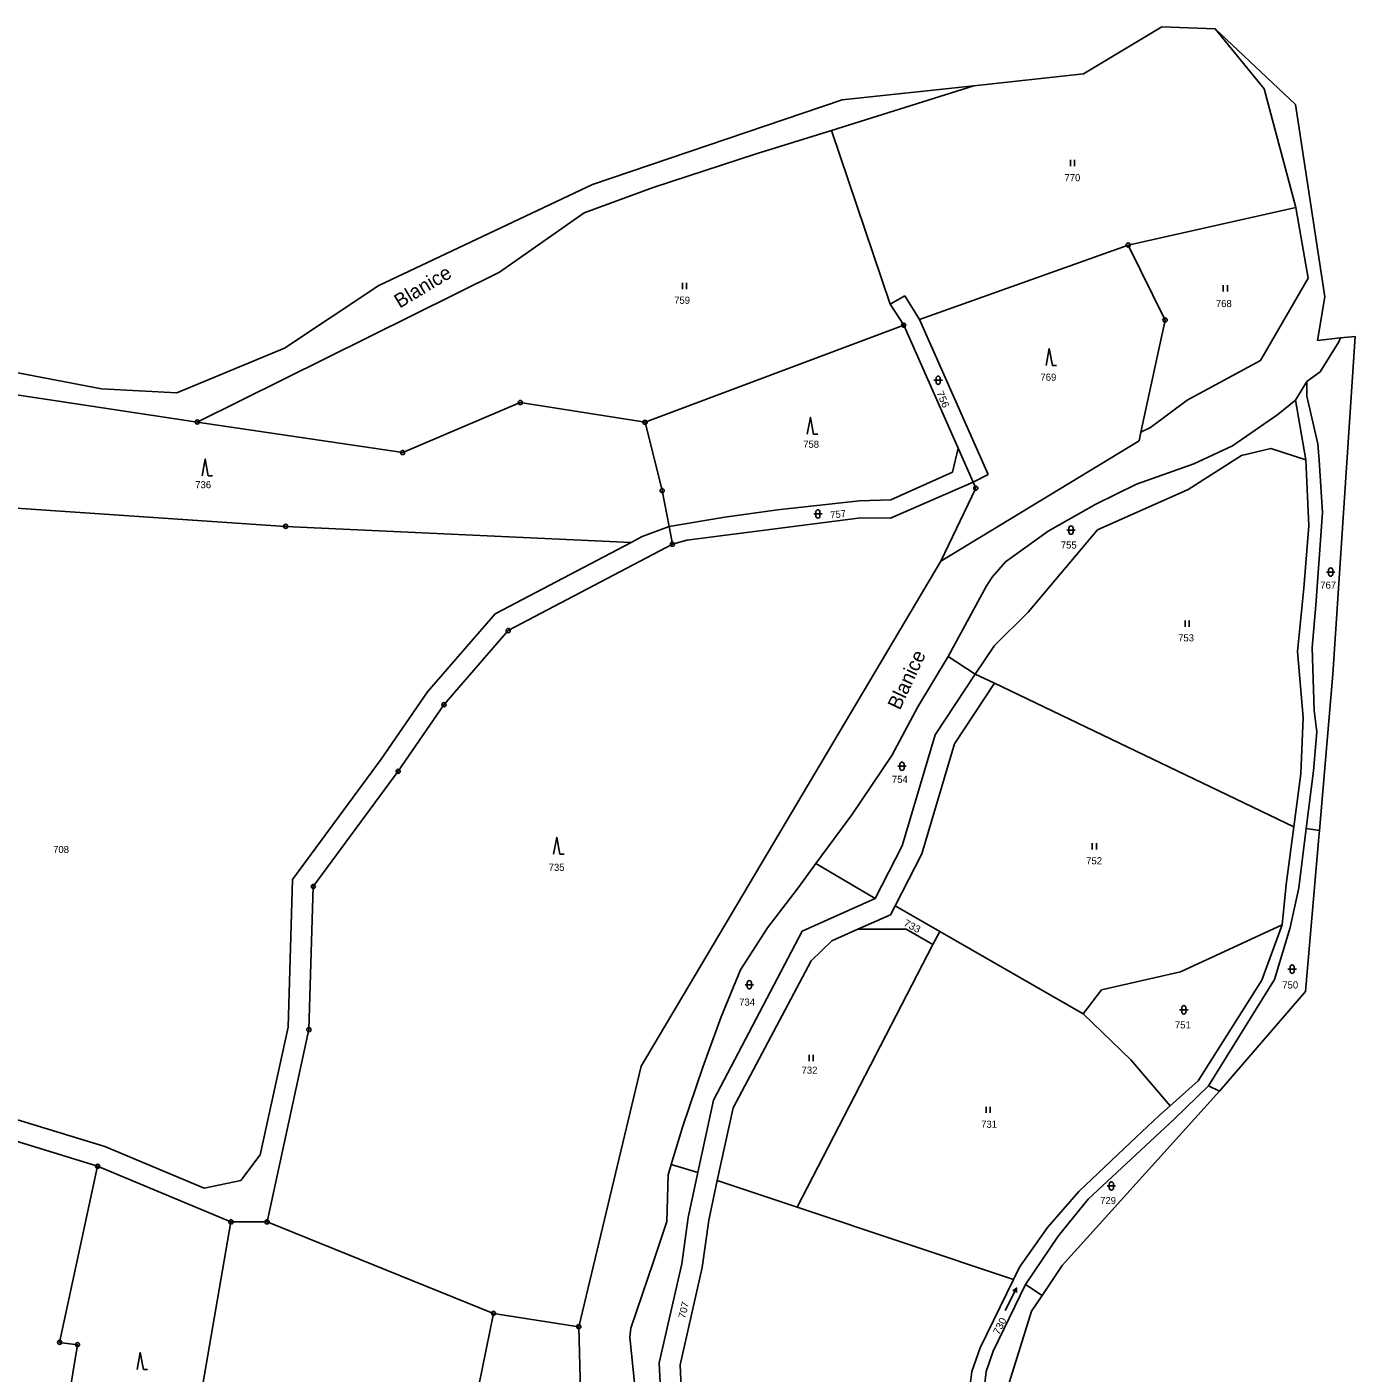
# Model space of a CAD drawing. Extents: x -719614 to -717765, y -1095834 to -1093862.
# Drawn here: x -718435.2 to -718117.4, y -1094701.4 to -1094379.3 of the extents above; entities that cross this region are included whole.
import ezdxf
from ezdxf.enums import TextEntityAlignment as Align

# ---------------------------------------------------------------- set-up
doc = ezdxf.new("R2010")
doc.units = 0
doc.header["$LTSCALE"] = 0.68
for name, color, linetype, lineweight in [('1', 7, 'Continuous', 25), ('3', 7, 'Continuous', 25), ('8', 7, 'Continuous', 25)]:
    doc.layers.add(name, color=color, linetype=linetype, lineweight=lineweight)
doc.layers.add('2', color=7, linetype='Continuous')
doc.layers.add('7', color=7, linetype='Continuous')

msp = doc.modelspace()

# ---------------------------------------------------------------- linework, layer by layer
at = {"layer": '1'}
for p, q in [((-718163.64, -1094379.29), (-718182.36, -1094390.55)), ((-718150.87, -1094379.77), (-718163.64, -1094379.29)), ((-718150.87, -1094379.77), (-718139.16, -1094394.12)), ((-718131.66, -1094397.89), (-718150.87, -1094379.77)), ((-718182.36, -1094390.55), (-718208.63, -1094393.36)), ((-718242.73, -1094404.04), (-718208.63, -1094393.36)), ((-718208.63, -1094393.36), (-718240.17, -1094396.73)), ((-718139.16, -1094394.12), (-718131.54, -1094422.53)), ((-718240.17, -1094396.73), (-718299.9, -1094416.98)), ((-718242.73, -1094404.04), (-718260.73, -1094409.67)), ((-718228.65, -1094445.61), (-718242.73, -1094404.04)), ((-718260.73, -1094409.67), (-718285.38, -1094417.73)), ((-718299.9, -1094416.98), (-718351.01, -1094441.13)), ((-718285.38, -1094417.73), (-718301.9, -1094423.77)), ((-718301.9, -1094423.77), (-718322.17, -1094438)), ((-718171.69, -1094431.47), (-718131.54, -1094422.53)), ((-718131.54, -1094422.53), (-718128.62, -1094439.38)), ((-718171.69, -1094431.47), (-718221.64, -1094449.3)), ((-718162.87, -1094449.43), (-718171.69, -1094431.47)), ((-718322.17, -1094438), (-718394.47, -1094473.83)), ((-718351.01, -1094441.13), (-718373.64, -1094456.15)), ((-718128.62, -1094439.38), (-718140.01, -1094459.1)), ((-718225.17, -1094443.64), (-718228.65, -1094445.61)), ((-718221.64, -1094449.3), (-718225.17, -1094443.64)), ((-718225.42, -1094450.65), (-718228.65, -1094445.61)), ((-718225.42, -1094450.65), (-718287.31, -1094473.89)), ((-718212.4, -1094480.08), (-718225.42, -1094450.65)), ((-718205.24, -1094486.39), (-718221.64, -1094449.3)), ((-718168.66, -1094476.22), (-718162.87, -1094449.43)), ((-718120.91, -1094453.71), (-718126.38, -1094454.33)), ((-718117.4, -1094453.32), (-718122.7, -1094534.11)), ((-718120.91, -1094453.71), (-718121.29, -1094454.67)), ((-718117.4, -1094453.32), (-718120.91, -1094453.71)), ((-718373.64, -1094456.15), (-718399.35, -1094466.81)), ((-718121.29, -1094454.67), (-718125.75, -1094461.81)), ((-718417.41, -1094465.85), (-718450.5, -1094459.53)), ((-718140.01, -1094459.1), (-718157.58, -1094468.63)), ((-718125.75, -1094461.81), (-718128.93, -1094464.13)), ((-718394.47, -1094473.83), (-718457.79, -1094464.33)), ((-718399.35, -1094466.81), (-718417.41, -1094465.85)), ((-718128.93, -1094464.13), (-718131.66, -1094468.58)), ((-718128.93, -1094464.13), (-718128.94, -1094467.67)), ((-718345.31, -1094481.13), (-718317.19, -1094469.16)), ((-718317.19, -1094469.16), (-718287.31, -1094473.89)), ((-718157.58, -1094468.63), (-718166.37, -1094475.12)), ((-718131.66, -1094468.58), (-718135.91, -1094472)), ((-718129.19, -1094482.89), (-718131.66, -1094468.58)), ((-718128.94, -1094467.67), (-718126.35, -1094479.01)), ((-718135.91, -1094472), (-718146.76, -1094479.49)), ((-718394.47, -1094473.83), (-718345.31, -1094481.13)), ((-718287.31, -1094473.89), (-718283.22, -1094490.22)), ((-718169.11, -1094478.3), (-718168.66, -1094476.22)), ((-718166.37, -1094475.12), (-718168.66, -1094476.22)), ((-718216.51, -1094507.09), (-718169.11, -1094478.3)), ((-718212.4, -1094480.08), (-718213.71, -1094485.83)), ((-718208.81, -1094488.2), (-718212.4, -1094480.08)), ((-718146.76, -1094479.49), (-718155.99, -1094483.8)), ((-718126.35, -1094479.01), (-718125.99, -1094482.97)), ((-718144.58, -1094481.83), (-718157.37, -1094489.97)), ((-718137.58, -1094480.17), (-718144.58, -1094481.83)), ((-718129.19, -1094482.89), (-718137.58, -1094480.17)), ((-718128.43, -1094498.63), (-718129.19, -1094482.89)), ((-718125.99, -1094482.97), (-718125.23, -1094495.48)), ((-718213.71, -1094485.83), (-718228.5, -1094492.45)), ((-718208.81, -1094488.2), (-718205.24, -1094486.39)), ((-718155.99, -1094483.8), (-718169.72, -1094488.68)), ((-718208.81, -1094488.2), (-718228.59, -1094496.86)), ((-718216.51, -1094507.09), (-718208.17, -1094489.65)), ((-718208.17, -1094489.65), (-718208.81, -1094488.2)), ((-718169.72, -1094488.68), (-718179.44, -1094493.45)), ((-718478.47, -1094491.73), (-718373.34, -1094498.79)), ((-718283.22, -1094490.22), (-718281.57, -1094498.84)), ((-718235.99, -1094492.7), (-718255.63, -1094494.87)), ((-718228.5, -1094492.45), (-718235.99, -1094492.7)), ((-718157.37, -1094489.97), (-718179.03, -1094499.58)), ((-718255.63, -1094494.87), (-718268.25, -1094496.56)), ((-718179.44, -1094493.45), (-718190.87, -1094499.93)), ((-718125.23, -1094495.48), (-718126.77, -1094517.65)), ((-718373.34, -1094498.79), (-718290.64, -1094502.61)), ((-718288.02, -1094501.23), (-718281.57, -1094498.84)), ((-718268.25, -1094496.56), (-718281.57, -1094498.84)), ((-718281.57, -1094498.84), (-718280.76, -1094503.06)), ((-718235.67, -1094496.71), (-718277.29, -1094502.12)), ((-718228.59, -1094496.86), (-718235.67, -1094496.71)), ((-718129.63, -1094513.59), (-718128.43, -1094498.63)), ((-718323.22, -1094519.73), (-718290.64, -1094502.61)), ((-718290.64, -1094502.61), (-718288.02, -1094501.23)), ((-718277.29, -1094502.12), (-718280.76, -1094503.06)), ((-718190.87, -1094499.93), (-718201.03, -1094507.28)), ((-718179.03, -1094499.58), (-718195.62, -1094519.29)), ((-718280.76, -1094503.06), (-718320.06, -1094523.72)), ((-718288.21, -1094627.97), (-718216.51, -1094507.09)), ((-718201.03, -1094507.28), (-718204.27, -1094510.96)), ((-718204.27, -1094510.96), (-718205.71, -1094513.17)), ((-718205.71, -1094513.17), (-718214.8, -1094529.89)), ((-718131.2, -1094528.71), (-718129.63, -1094513.59)), ((-718126.77, -1094517.65), (-718127.7, -1094527.79)), ((-718339.4, -1094538.4), (-718323.22, -1094519.73)), ((-718195.62, -1094519.29), (-718203.69, -1094527.32)), ((-718320.06, -1094523.72), (-718335.44, -1094541.46)), ((-718203.69, -1094527.32), (-718208.32, -1094534.13)), ((-718127.7, -1094527.79), (-718127.17, -1094542.81)), ((-718214.8, -1094529.89), (-718222.01, -1094541.95)), ((-718214.8, -1094529.89), (-718208.32, -1094534.13)), ((-718129.83, -1094544.55), (-718131.2, -1094528.71)), ((-718217.88, -1094548.64), (-718208.32, -1094534.13)), ((-718208.32, -1094534.13), (-718203.67, -1094536.34)), ((-718125.92, -1094571.53), (-718122.7, -1094534.11)), ((-718203.67, -1094536.34), (-718213.3, -1094550.78)), ((-718203.67, -1094536.34), (-718132.06, -1094570.7)), ((-718350.47, -1094554.49), (-718339.4, -1094538.4)), ((-718335.44, -1094541.46), (-718346.4, -1094557.39)), ((-718222.01, -1094541.95), (-718228.22, -1094553.62)), ((-718130.38, -1094557.97), (-718129.83, -1094544.55)), ((-718127.17, -1094542.81), (-718126.55, -1094547.95)), ((-718225.78, -1094575.26), (-718217.88, -1094548.64)), ((-718213.3, -1094550.78), (-718221.12, -1094577.12)), ((-718126.55, -1094547.95), (-718127.39, -1094557.29)), ((-718228.22, -1094553.62), (-718237.86, -1094567.83)), ((-718371.66, -1094583.24), (-718350.47, -1094554.49)), ((-718346.4, -1094557.39), (-718366.71, -1094584.95)), ((-718127.39, -1094557.29), (-718129.13, -1094571.11)), ((-718132.06, -1094570.7), (-718130.38, -1094557.97)), ((-718133.87, -1094584.48), (-718132.06, -1094570.7)), ((-718129.13, -1094571.11), (-718130.9, -1094585.23)), ((-718126.06, -1094573.17), (-718129.29, -1094610.09)), ((-718129.13, -1094571.11), (-718125.92, -1094571.53)), ((-718126.06, -1094573.17), (-718125.92, -1094571.53)), ((-718232.21, -1094587.86), (-718225.78, -1094575.26)), ((-718246.42, -1094579.44), (-718250.7, -1094585.24)), ((-718221.12, -1094577.12), (-718227.48, -1094589.61)), ((-718372.74, -1094618.58), (-718371.66, -1094583.24)), ((-718366.71, -1094584.95), (-718367.76, -1094619.19)), ((-718250.7, -1094585.24), (-718257.98, -1094594.88)), ((-718134.87, -1094594.13), (-718133.87, -1094584.48)), ((-718130.9, -1094585.23), (-718132.97, -1094594.74)), ((-718249.72, -1094595.65), (-718232.21, -1094587.86)), ((-718227.48, -1094589.61), (-718228.56, -1094591.71)), ((-718216.8, -1094595.73), (-718227.48, -1094589.61)), ((-718228.56, -1094591.71), (-718236.37, -1094595.18)), ((-718270.97, -1094636.07), (-718249.72, -1094595.65)), ((-718257.98, -1094594.88), (-718264.47, -1094604.85)), ((-718236.37, -1094595.18), (-718242.62, -1094597.96)), ((-718236.37, -1094595.18), (-718224.8, -1094595.18)), ((-718224.8, -1094595.18), (-718218.41, -1094598.84)), ((-718218.41, -1094598.84), (-718216.8, -1094595.73)), ((-718216.8, -1094595.73), (-718182.49, -1094615.4)), ((-718134.87, -1094594.13), (-718159.16, -1094605.4)), ((-718139.71, -1094607.37), (-718134.87, -1094594.13)), ((-718132.97, -1094594.74), (-718136.69, -1094607.24)), ((-718218.41, -1094598.84), (-718250.93, -1094661.69)), ((-718242.62, -1094597.96), (-718247.55, -1094602.75)), ((-718264.47, -1094604.85), (-718269.11, -1094616.13)), ((-718247.55, -1094602.75), (-718266.25, -1094637.88)), ((-718159.16, -1094605.4), (-718178.1, -1094609.66)), ((-718154.99, -1094631.44), (-718139.71, -1094607.37)), ((-718136.69, -1094607.24), (-718152.49, -1094632.62)), ((-718178.1, -1094609.66), (-718182.49, -1094615.4)), ((-718129.29, -1094610.09), (-718149.87, -1094633.94)), ((-718182.49, -1094615.4), (-718171.06, -1094626.42)), ((-718379.39, -1094649.16), (-718372.74, -1094618.58)), ((-718269.11, -1094616.13), (-718273.48, -1094628.14)), ((-718367.76, -1094619.19), (-718377.76, -1094665.2)), ((-718303.17, -1094690.28), (-718288.21, -1094627.97)), ((-718273.48, -1094628.14), (-718278.27, -1094642.28)), ((-718171.06, -1094626.42), (-718161.67, -1094637.39)), ((-718161.67, -1094637.39), (-718154.99, -1094631.44)), ((-718149.87, -1094633.94), (-718187.47, -1094675.62)), ((-718152.49, -1094632.62), (-718160.65, -1094640.54)), ((-718152.49, -1094632.62), (-718149.87, -1094633.94)), ((-718450.16, -1094636.86), (-718416.62, -1094647.19)), ((-718274.7, -1094653.36), (-718270.97, -1094636.07)), ((-718266.25, -1094637.88), (-718270.02, -1094655.33)), ((-718164.37, -1094639.8), (-718161.67, -1094637.39)), ((-718160.65, -1094640.54), (-718181.3, -1094659.75)), ((-718171.16, -1094646.21), (-718164.37, -1094639.8)), ((-718418.32, -1094651.9), (-718451.67, -1094641.63)), ((-718278.27, -1094642.28), (-718281.04, -1094651.48)), ((-718416.62, -1094647.19), (-718392.85, -1094657.1)), ((-718183.53, -1094657.89), (-718171.16, -1094646.21)), ((-718384.07, -1094655.33), (-718379.39, -1094649.16)), ((-718427.41, -1094694.02), (-718418.32, -1094651.9)), ((-718386.43, -1094665.2), (-718418.32, -1094651.9)), ((-718281.78, -1094653.94), (-718282.1, -1094665.12)), ((-718281.04, -1094651.48), (-718281.78, -1094653.94)), ((-718274.7, -1094653.36), (-718281.04, -1094651.48)), ((-718277.02, -1094664.11), (-718274.7, -1094653.36)), ((-718392.85, -1094657.1), (-718384.07, -1094655.33)), ((-718270.02, -1094655.33), (-718272.07, -1094664.79)), ((-718250.93, -1094661.69), (-718270.02, -1094655.33)), ((-718191, -1094666.56), (-718183.53, -1094657.89)), ((-718181.3, -1094659.75), (-718188.47, -1094668.63)), ((-718250.93, -1094661.69), (-718199.15, -1094678.94)), ((-718401.57, -1094752.45), (-718386.43, -1094665.2)), ((-718377.76, -1094665.2), (-718386.43, -1094665.2)), ((-718377.76, -1094665.2), (-718323.58, -1094687.09)), ((-718282.1, -1094665.12), (-718285.3, -1094674.7)), ((-718278.55, -1094675.24), (-718277.02, -1094664.11)), ((-718272.07, -1094664.79), (-718273.63, -1094676.13)), ((-718197.73, -1094676.03), (-718191, -1094666.56)), ((-718188.47, -1094668.63), (-718196.25, -1094680.16)), ((-718285.3, -1094674.7), (-718290.71, -1094690.65)), ((-718283.9, -1094698.94), (-718278.55, -1094675.24)), ((-718273.63, -1094676.13), (-718278.88, -1094699.39)), ((-718199.15, -1094678.94), (-718197.73, -1094676.03)), ((-718192.32, -1094682.83), (-718187.47, -1094675.62)), ((-718207.16, -1094695.34), (-718199.15, -1094678.94)), ((-718204, -1094696.13), (-718196.25, -1094680.16)), ((-718196.25, -1094680.16), (-718192.32, -1094682.83)), ((-718194.83, -1094686.56), (-718192.32, -1094682.83)), ((-718323.58, -1094687.09), (-718338.19, -1094759.09)), ((-718303.17, -1094690.28), (-718323.58, -1094687.09)), ((-718194.83, -1094686.56), (-718201.68, -1094708.56)), ((-718302.75, -1094705.74), (-718303.17, -1094690.28)), ((-718290.71, -1094690.65), (-718290.93, -1094692.81)), ((-718431.06, -1094742.32), (-718423.14, -1094694.58)), ((-718423.14, -1094694.58), (-718427.41, -1094694.02)), ((-718290.93, -1094692.81), (-718289.77, -1094704.51)), ((-718209.14, -1094700.98), (-718207.16, -1094695.34)), ((-718283.36, -1094711.58), (-718283.9, -1094698.94)), ((-718205.66, -1094701), (-718204, -1094696.13)), ((-718278.88, -1094699.39), (-718278.37, -1094711.2)), ((-718211.58, -1094721.22), (-718209.14, -1094700.98)), ((-718208.16, -1094722.43), (-718205.66, -1094701))]:
    msp.add_line(p, q, dxfattribs=at)
for points in [[(-718126.38, -1094454.33), (-718124.62, -1094443.85), (-718131.66, -1094397.89)], [(-718237.86, -1094567.83), (-718246.42, -1094579.44), (-718232.21, -1094587.86)]]:
    msp.add_lwpolyline(points, dxfattribs=at)
at = {"layer": '3'}
for p, q in [((-718185.511, -1094412.59), (-718185.511, -1094411.09)), ((-718184.51, -1094412.59), (-718184.51, -1094411.09)), ((-718278.391, -1094442.03), (-718278.391, -1094440.53)), ((-718277.39, -1094442.03), (-718277.39, -1094440.53)), ((-718148.931, -1094442.59), (-718148.931, -1094441.09)), ((-718147.93, -1094442.59), (-718147.93, -1094441.09)), ((-718189.84, -1094460.26), (-718188.844, -1094460.26)), ((-718218.171, -1094463.841), (-718216.169, -1094463.841)), ((-718217.671, -1094463.341), (-718217.671, -1094464.342)), ((-718216.669, -1094464.342), (-718216.669, -1094463.341)), ((-718247, -1094476.71), (-718246.004, -1094476.71)), ((-718391.83, -1094486.67), (-718390.834, -1094486.67)), ((-718246.961, -1094495.821), (-718244.959, -1094495.821)), ((-718246.461, -1094495.321), (-718246.461, -1094496.322)), ((-718245.459, -1094496.322), (-718245.459, -1094495.321)), ((-718185.901, -1094499.191), (-718185.901, -1094500.192)), ((-718184.899, -1094500.192), (-718184.899, -1094499.191)), ((-718186.401, -1094499.691), (-718184.399, -1094499.691)), ((-718124.241, -1094509.721), (-718122.239, -1094509.721)), ((-718123.741, -1094509.221), (-718123.741, -1094510.222)), ((-718122.739, -1094510.222), (-718122.739, -1094509.221)), ((-718158.071, -1094522.84), (-718158.071, -1094521.34)), ((-718157.07, -1094522.84), (-718157.07, -1094521.34)), ((-718226.831, -1094556.181), (-718224.829, -1094556.181)), ((-718226.331, -1094555.681), (-718226.331, -1094556.682)), ((-718225.329, -1094556.682), (-718225.329, -1094555.681)), ((-718180.281, -1094576.1), (-718180.281, -1094574.6)), ((-718179.28, -1094576.1), (-718179.28, -1094574.6)), ((-718307.7, -1094577.22), (-718306.704, -1094577.22)), ((-718133.461, -1094604.731), (-718131.459, -1094604.731)), ((-718132.961, -1094604.231), (-718132.961, -1094605.232)), ((-718131.959, -1094605.232), (-718131.959, -1094604.231)), ((-718263.351, -1094608.461), (-718261.349, -1094608.461)), ((-718262.851, -1094607.961), (-718262.851, -1094608.962)), ((-718261.849, -1094608.962), (-718261.849, -1094607.961)), ((-718159.381, -1094614.461), (-718157.379, -1094614.461)), ((-718158.881, -1094613.961), (-718158.881, -1094614.962)), ((-718157.879, -1094614.962), (-718157.879, -1094613.961)), ((-718248.051, -1094626.76), (-718248.051, -1094625.26)), ((-718247.05, -1094626.76), (-718247.05, -1094625.26)), ((-718205.711, -1094639.13), (-718205.711, -1094637.63)), ((-718204.71, -1094639.13), (-718204.71, -1094637.63)), ((-718176.711, -1094656.591), (-718174.709, -1094656.591)), ((-718176.211, -1094656.091), (-718176.211, -1094657.092)), ((-718175.209, -1094657.092), (-718175.209, -1094656.091)), ((-718198.403, -1094681.016), (-718198.399, -1094682.114)), ((-718407.36, -1094700.48), (-718406.364, -1094700.48))]:
    msp.add_line(p, q, dxfattribs=at)
for points in [[(-718189.84, -1094460.26), (-718190.59, -1094456.26), (-718191.34, -1094460.26)], [(-718247, -1094476.71), (-718247.75, -1094472.71), (-718248.5, -1094476.71)], [(-718391.83, -1094486.67), (-718392.58, -1094482.67), (-718393.33, -1094486.67)], [(-718307.7, -1094577.22), (-718308.45, -1094573.22), (-718309.2, -1094577.22)], [(-718201.127, -1094686.362), (-718198.403, -1094681.016), (-718199.293, -1094681.659)], [(-718407.36, -1094700.48), (-718408.11, -1094696.48), (-718408.86, -1094700.48)]]:
    msp.add_lwpolyline(points, dxfattribs=at)
for centre, start, end in [((-718217.17, -1094463.3409), 0, 180), ((-718217.17, -1094464.3409), 180, 359.98789), ((-718245.96, -1094495.3209), 0, 180), ((-718245.96, -1094496.3209), 180, 359.98789), ((-718185.4, -1094499.1909), 0, 180), ((-718185.4, -1094500.1909), 180, 359.98789), ((-718123.24, -1094509.2209), 0, 180), ((-718123.24, -1094510.2209), 180, 359.98789), ((-718225.83, -1094555.6809), 0, 180), ((-718225.83, -1094556.6809), 180, 359.98789), ((-718132.46, -1094604.2309), 0, 180), ((-718132.46, -1094605.2309), 180, 359.98789), ((-718262.35, -1094607.9609), 0, 180), ((-718262.35, -1094608.9609), 180, 359.98789), ((-718158.38, -1094613.9609), 0, 180), ((-718158.38, -1094614.9609), 180, 359.98789), ((-718175.71, -1094656.0909), 0, 180), ((-718175.71, -1094657.0909), 180, 359.98789)]:
    msp.add_arc(centre, 0.5, start, end, dxfattribs=at)
at = {"layer": '8'}
for centre, radius in [((-718171.69, -1094431.4699), 0.5), ((-718171.69, -1094431.4699), 0.0303), ((-718225.42, -1094450.6499), 0.5), ((-718225.42, -1094450.6499), 0.0303), ((-718162.87, -1094449.4299), 0.5), ((-718162.87, -1094449.4299), 0.0303), ((-718317.19, -1094469.1599), 0.5), ((-718317.19, -1094469.1599), 0.0303), ((-718394.47, -1094473.8299), 0.5), ((-718287.31, -1094473.8899), 0.5), ((-718394.47, -1094473.8299), 0.0303), ((-718287.31, -1094473.8899), 0.0303), ((-718345.31, -1094481.1299), 0.5), ((-718345.31, -1094481.1299), 0.0303), ((-718283.22, -1094490.2199), 0.5), ((-718208.17, -1094489.6499), 0.5), ((-718208.17, -1094489.6499), 0.0303), ((-718283.22, -1094490.2199), 0.0303), ((-718373.34, -1094498.7899), 0.5), ((-718373.34, -1094498.7899), 0.0303), ((-718280.76, -1094503.0599), 0.5), ((-718280.76, -1094503.0599), 0.0303), ((-718320.06, -1094523.7199), 0.5), ((-718320.06, -1094523.7199), 0.0303), ((-718335.44, -1094541.4599), 0.5), ((-718335.44, -1094541.4599), 0.0303), ((-718346.4, -1094557.3899), 0.5), ((-718346.4, -1094557.3899), 0.0303), ((-718366.71, -1094584.9499), 0.5), ((-718366.71, -1094584.9499), 0.0303), ((-718367.76, -1094619.1899), 0.5), ((-718367.76, -1094619.1899), 0.0303), ((-718418.32, -1094651.8999), 0.5), ((-718418.32, -1094651.8999), 0.0303), ((-718386.43, -1094665.1999), 0.5), ((-718386.43, -1094665.1999), 0.0303), ((-718377.76, -1094665.1999), 0.5), ((-718377.76, -1094665.1999), 0.0303), ((-718323.58, -1094687.0899), 0.5), ((-718323.58, -1094687.0899), 0.0303), ((-718303.17, -1094690.2799), 0.5), ((-718303.17, -1094690.2799), 0.0303), ((-718427.41, -1094694.0199), 0.5), ((-718427.41, -1094694.0199), 0.0303), ((-718423.14, -1094694.5799), 0.5), ((-718423.14, -1094694.5799), 0.0303)]:
    msp.add_circle(centre, radius, dxfattribs=at)

# ---------------------------------------------------------------- texts
at = {"layer": '2'}
for s, p in [('770', (-718185.049, -1094416.202)), ('759', (-718278.459, -1094445.542)), ('768', (-718148.809, -1094446.332)), ('769', (-718190.799, -1094463.942)), ('758', (-718247.579, -1094479.982)), ('736', (-718393.059, -1094489.652)), ('755', (-718185.919, -1094504.092)), ('767', (-718123.839, -1094513.702)), ('753', (-718157.849, -1094526.312)), ('754', (-718226.349, -1094560.162)), ('708', (-718427.069, -1094576.942)), ('735', (-718308.489, -1094581.202)), ('752', (-718179.849, -1094579.642)), ('750', (-718132.919, -1094609.352)), ('734', (-718262.889, -1094613.452)), ('751', (-718158.619, -1094618.892)), ('732', (-718247.959, -1094629.742)), ('731', (-718204.989, -1094642.682)), ('729', (-718176.519, -1094660.932))]:
    msp.add_text(s, height=1.7, dxfattribs=at).set_placement(p, align=Align.CENTER)
for s, rotation, width, p in [('756', 293, 1.1, (-718216.8083, -1094468.6999)), ('733', 332, 1.1, (-718223.7781, -1094595.1899)), ('707', 76, 1.05, (-718277.2585, -1094686.4956)), ('730', 63, 1.1, (-718201.6865, -1094690.4859))]:
    msp.add_text(s, height=1.7, rotation=rotation, dxfattribs=dict(at, width=width)).set_placement(p, align=Align.CENTER)
msp.add_text('757', height=1.7, rotation=7, dxfattribs=at).set_placement((-718241.0306, -1094496.7261), align=Align.CENTER)
at = {"layer": '7'}
for rotation, p in [(31, (-718339.6561, -1094442.8706)), (65, (-718223.1884, -1094536.1725))]:
    msp.add_text('Blanice', height=3.4, rotation=rotation, dxfattribs=at).set_placement(p, align=Align.CENTER)

doc.saveas('drawing.dxf')
